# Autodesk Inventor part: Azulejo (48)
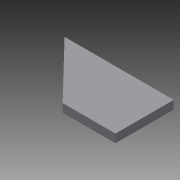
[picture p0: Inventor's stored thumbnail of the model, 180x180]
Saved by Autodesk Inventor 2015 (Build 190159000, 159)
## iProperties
Created: 2015-04
Part Number: Azulejo (48)
Material: Genérico
Document SubType Name: Modeling
Designer: Felipe
Density: 1 g/cm^3
Appearance: Padrão
Author: Felipe
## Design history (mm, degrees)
sketch "Sketch1"
  geometry: L1 (-5999.978, 1162.687)-(-5915.126, 1162.687); L2 (6980.022, 1162.687)-(6895.169, 1162.687); L3 (-1034.12, -6357.313)-(-1063.775, -6417.313); L4 (-5519.978, 1582.687)-(-6306.841, 1582.687); L5 (5000.022, -4857.313)-(6000.022, -4857.313); L6 (6000.022, -4857.313)-(6000.022, -6277.313); L7 (6000.022, -4837.313)-(5000.022, -4837.313); L8 (5000.022, -4837.313)-(5000.022, -3357.313); L9 (5000.022, -3357.313)-(6000.022, -3357.313); L10 (6000.022, -3357.313)-(6000.022, -4837.313); L11 (6000.022, -3337.313)-(5000.022, -3337.313); L12 (5000.022, -3337.313)-(5000.022, -1857.313); L13 (5000.022, -1857.313)-(6000.022, -1857.313); L14 (6000.022, -1857.313)-(6000.022, -3337.313); L15 (6000.022, -1837.313)-(5000.022, -1837.313); L16 (5000.022, -1837.313)-(5000.022, -357.313); L17 (5000.022, -357.313)-(6000.022, -357.313); L18 (6000.022, -357.313)-(6000.022, -1837.313); L19 (4000.022, -4837.313)-(3500.022, -4837.313); L20 (3500.022, -4837.313)-(3500.022, -3357.313); L21 (3500.022, -3357.313)-(4000.022, -3357.313); L22 (4000.022, -3357.313)-(4000.022, -4837.313); L23 (4000.022, -3337.313)-(3500.022, -3337.313); L24 (3500.022, -3337.313)-(3500.022, -1857.313); L25 (2000.022, 2662.687)-(2480.022, 2662.687); L26 (500.022, 2662.687)-(1980.022, 2662.687); L27 (-999.978, 2662.687)-(480.022, 2662.687); L28 (3500.022, -1857.313)-(4000.022, -1857.313); L29 (4000.022, -1857.313)-(4000.022, -3337.313); L30 (4000.022, -1837.313)-(3500.022, -1837.313); L31 (3500.022, -1837.313)-(3500.022, -357.313); L32 (3500.022, -357.313)-(4000.022, -357.313); L33 (4000.022, -357.313)-(4000.022, -1837.313); L34 (-5519.978, 1142.687)-(-5519.978, -337.313); L35 (6500.022, -337.313)-(6500.022, 1142.687); L36 (6480.022, 2662.687)-(5000.022, 2662.687); L37 (5000.022, 2642.687)-(6480.022, 2642.687); L38 (6480.022, 1142.687)-(6480.022, -337.313); L39 (6480.022, -337.313)-(5000.022, -337.313); L40 (5000.022, -337.313)-(5000.022, 1142.687); L41 (7965.922, 2662.687)-(6500.022, 2662.687); L42 (6500.022, 2642.687)-(7965.922, 2642.687); L43 (4980.022, 2662.687)-(3500.022, 2662.687); L44 (3500.022, 2642.687)-(4980.022, 2642.687); L45 (4980.022, 1142.687)-(4980.022, -337.313); L46 (4980.022, -337.313)-(3500.022, -337.313); L47 (3500.022, -337.313)-(3500.022, 1142.687); L48 (3500.022, -1837.313)-(3500.022, -357.313); L49 (3500.022, -3337.313)-(3500.022, -1857.313); L50 (3500.022, -4837.313)-(3500.022, -3357.313); L51 (3500.022, -6257.313)-(3500.022, -4857.313); L52 (4000.022, -6277.313)-(3500.022, -6277.313); L53 (3500.022, -6277.313)-(3500.022, -4857.313); L54 (3480.022, 1162.687)-(2000.022, 1162.687); L55 (2000.022, 1142.687)-(3480.022, 1142.687); L56 (3480.022, 1142.687)-(3480.022, -337.313); L57 (3480.022, -337.313)-(2000.022, -337.313); L58 (2000.022, -337.313)-(2000.022, 1142.687); L59 (3480.022, -357.313)-(3480.022, -1837.313); L60 (3480.022, -1857.313)-(3480.022, -3337.313); L61 (3480.022, -3357.313)-(3480.022, -4837.313); L62 (3480.022, -4857.313)-(3480.022, -6277.313); L63 (3500.022, -4857.313)-(4000.022, -4857.313); L64 (1980.022, 1162.687)-(500.022, 1162.687)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; 4 further points
  constraints: 1802 end point, 96 point on line, 2 other
extrude "Extrusion1" new body sketch "Sketch1" distance "d0" = 60; taper "d1" = 0 deg
body "Solid1"
